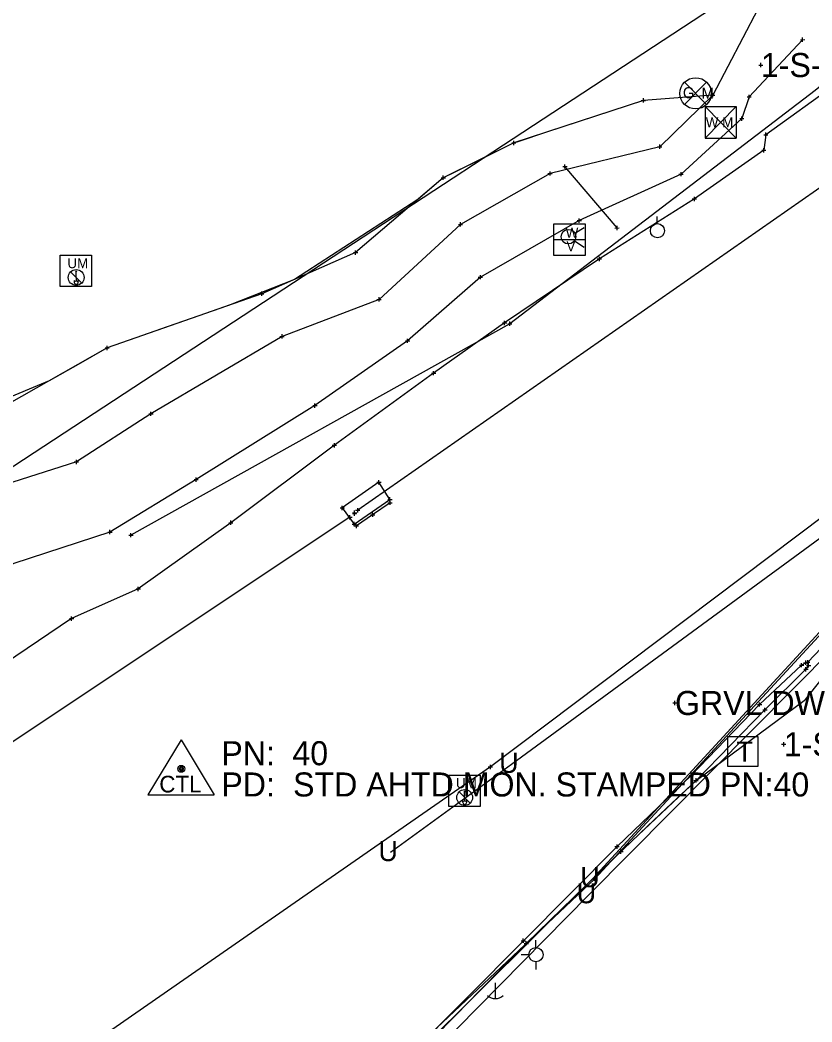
# Model space of a CAD drawing. Extents: x -1 to 1157254, y -1 to 2021979.
# Drawn here: x 1146373.4 to 1146610.6, y 2016480.3 to 2016780.3 of the extents above; entities that cross this region are included whole.
import ezdxf

# ---------------------------------------------------------------- set-up
doc = ezdxf.new("R2010")
doc.units = 0
for name, color, linetype in [('S_AREA_CALC', 7, 'Continuous'), ('S_BUILDING_ANNOT', 7, 'Continuous'), ('S_CAL_CORNER', 7, 'Continuous'), ('S_CAL_CORNER_ANNOT', 7, 'Continuous'), ('S_CATCH_BASIN', 7, 'Continuous'), ('S_CATCH_BASIN_ANNOT', 7, 'Continuous'), ('S_CONTOUR_ANNOT', 7, 'Continuous'), ('S_CONTOUR_MAJOR', 7, 'Continuous'), ('S_CTL_TABLE', 7, 'Continuous'), ('S_DITCHLINE', 7, 'Continuous'), ('S_DRIVEWAY_ANNOT', 7, 'Continuous'), ('S_DROP_INLET', 7, 'Continuous'), ('S_DROP_INLET_ANNOT', 7, 'Continuous'), ('S_DTM_PAVEMENT', 7, 'Continuous'), ('S_EDGE_BITUMINOUS_ANNOT', 7, 'Continuous'), ('S_ELECTRIC_UTILITIES', 7, 'Continuous'), ('S_FENCE', 7, 'Continuous'), ('S_GAS_PUMP_ISLAND_ANNOT', 7, 'Continuous'), ('S_GAS_UTILITIES', 7, 'Continuous'), ('S_GATE', 7, 'Continuous')]:
    doc.layers.add(name, color=color, linetype=linetype)

msp = doc.modelspace()

# ---------------------------------------------------------------- linework, layer by layer
at = {"layer": 'S_AREA_CALC'}
for p, q in [((1146421.68, 2016564.82), (1146411.65, 2016548.31)), ((1146421.68, 2016564.82), (1146431.5, 2016548.31)), ((1146411.65, 2016548.31), (1146431.5, 2016548.31))]:
    msp.add_line(p, q, dxfattribs=at)
for radius in [1.04, 0.609, 0.344]:
    msp.add_circle((1146421.68, 2016556.12), radius, dxfattribs=at)
at = {"layer": 'S_BUILDING_ANNOT'}
for p, q in [((1146594.63, 2016766.86), (1146595.9, 2016766.87)), ((1146595.27, 2016766.23), (1146595.27, 2016767.5)), ((1146595.27, 2016766.87), (1146595.27, 2016766.87)), ((1146535.95, 2016736.48), (1146537.22, 2016736.48)), ((1146536.59, 2016735.85), (1146536.58, 2016737.12)), ((1146536.59, 2016736.48), (1146536.59, 2016736.48)), ((1146551.58, 2016718.07), (1146552.85, 2016718.08)), ((1146552.22, 2016717.44), (1146552.22, 2016718.71)), ((1146552.22, 2016718.08), (1146552.22, 2016718.08)), ((1146519.44, 2016689.4), (1146520.71, 2016689.4)), ((1146520.07, 2016688.77), (1146520.07, 2016690.04)), ((1146520.07, 2016689.4), (1146520.07, 2016689.4)), ((1146480.24, 2016641.94), (1146481.51, 2016641.94)), ((1146480.87, 2016641.3), (1146480.87, 2016642.57)), ((1146480.87, 2016641.94), (1146480.87, 2016641.94)), ((1146484.19, 2016636.16), (1146484.18, 2016637.43)), ((1146469.25, 2016634.27), (1146470.52, 2016634.27)), ((1146469.88, 2016633.63), (1146469.88, 2016634.9)), ((1146469.88, 2016634.27), (1146469.88, 2016634.27)), ((1146474.52, 2016632.93), (1146474.52, 2016634.21)), ((1146483.55, 2016636.79), (1146484.82, 2016636.8)), ((1146484.19, 2016636.79), (1146484.19, 2016636.79)), ((1146471.55, 2016631.44), (1146472.82, 2016631.44)), ((1146472.19, 2016630.81), (1146472.19, 2016632.08)), ((1146472.19, 2016631.44), (1146472.19, 2016631.44)), ((1146472.92, 2016632.56), (1146474.2, 2016632.57)), ((1146472.96, 2016632.8), (1146474.23, 2016632.81)), ((1146473.56, 2016631.93), (1146473.56, 2016633.2)), ((1146473.56, 2016632.57), (1146473.56, 2016632.57)), ((1146473.6, 2016632.17), (1146473.59, 2016633.44)), ((1146473.6, 2016632.81), (1146473.6, 2016632.81)), ((1146473.88, 2016633.57), (1146475.16, 2016633.57)), ((1146474.52, 2016633.57), (1146474.52, 2016633.57)), ((1146472.85, 2016629.43), (1146474.12, 2016629.43)), ((1146473.48, 2016628.8), (1146473.48, 2016630.07)), ((1146473.48, 2016629.43), (1146473.48, 2016629.43)), ((1146405.96, 2016626.09), (1146407.23, 2016626.1)), ((1146406.59, 2016625.46), (1146406.59, 2016626.73)), ((1146406.59, 2016626.1), (1146406.59, 2016626.1)), ((1146606.85, 2016587.16), (1146608.12, 2016587.16)), ((1146607.49, 2016586.52), (1146607.48, 2016587.8)), ((1146607.49, 2016587.16), (1146607.49, 2016587.16)), ((1146608.06, 2016587.9), (1146609.33, 2016587.9)), ((1146608.7, 2016587.26), (1146608.7, 2016588.54)), ((1146608.7, 2016587.9), (1146608.7, 2016587.9)), ((1146608.71, 2016588.04), (1146609.99, 2016588.05)), ((1146608.78, 2016585.31), (1146608.78, 2016586.58)), ((1146608.95, 2016587.1), (1146610.22, 2016587.1)), ((1146609.35, 2016587.41), (1146609.35, 2016588.68)), ((1146609.35, 2016588.04), (1146609.35, 2016588.04)), ((1146609.58, 2016586.46), (1146609.58, 2016587.73)), ((1146609.58, 2016587.1), (1146609.58, 2016587.1)), ((1146608.14, 2016585.94), (1146609.41, 2016585.95)), ((1146608.78, 2016585.95), (1146608.78, 2016585.95)), ((1146568.9, 2016575.84), (1146570.18, 2016575.84)), ((1146569.54, 2016575.2), (1146569.54, 2016576.47)), ((1146569.54, 2016575.84), (1146569.54, 2016575.84)), ((1146594.26, 2016575.38), (1146595.53, 2016575.38)), ((1146594.9, 2016574.75), (1146594.89, 2016576.02)), ((1146594.9, 2016575.38), (1146594.9, 2016575.38)), ((1146596.5, 2016573.12), (1146596.5, 2016574.39)), ((1146595.86, 2016573.76), (1146597.13, 2016573.76)), ((1146596.5, 2016573.76), (1146596.5, 2016573.76)), ((1146601.49, 2016563.49), (1146602.77, 2016563.49)), ((1146602.13, 2016562.86), (1146602.13, 2016564.13)), ((1146602.13, 2016563.49), (1146602.13, 2016563.49)), ((1146513.63, 2016556.71), (1146514.9, 2016556.71)), ((1146514.27, 2016556.07), (1146514.26, 2016557.34)), ((1146514.26, 2016556.71), (1146514.26, 2016556.71)), ((1146573.79, 2016554.17), (1146575.06, 2016554.17)), ((1146574.43, 2016553.54), (1146574.42, 2016554.81)), ((1146574.42, 2016554.17), (1146574.42, 2016554.17)), ((1146575.86, 2016552.04), (1146575.86, 2016553.32)), ((1146575.22, 2016552.68), (1146576.49, 2016552.68)), ((1146575.86, 2016552.68), (1146575.86, 2016552.68)), ((1146551.56, 2016532.83), (1146552.83, 2016532.83)), ((1146552.2, 2016532.2), (1146552.19, 2016533.47)), ((1146552.2, 2016532.83), (1146552.2, 2016532.83)), ((1146552.72, 2016531.33), (1146553.99, 2016531.34)), ((1146553.36, 2016530.7), (1146553.35, 2016531.97)), ((1146553.36, 2016531.33), (1146553.36, 2016531.33)), ((1146544.89, 2016523.15), (1146546.16, 2016523.15)), ((1146545.53, 2016522.52), (1146545.52, 2016523.79)), ((1146545.52, 2016523.15), (1146545.52, 2016523.15)), ((1146524.14, 2016504), (1146524.13, 2016505.28)), ((1146523.5, 2016504.64), (1146524.77, 2016504.64)), ((1146524.14, 2016504.64), (1146524.14, 2016504.64)), ((1146524.37, 2016503.84), (1146525.65, 2016503.85)), ((1146525.01, 2016503.21), (1146525.01, 2016504.48)), ((1146525.01, 2016503.84), (1146525.01, 2016503.84))]:
    msp.add_line(p, q, dxfattribs=at)
at = {"layer": 'S_CAL_CORNER'}
for p, q in [((1146388.53, 2016704.93), (1146391.86, 2016701.6)), ((1146390.04, 2016705.16), (1146390.35, 2016705.16)), ((1146390.2, 2016703.27), (1146390.2, 2016705)), ((1146390.2, 2016703.27), (1146390.2, 2016702.21)), ((1146389.6, 2016702.36), (1146389.6, 2016702.18)), ((1146390.79, 2016702.37), (1146390.8, 2016702.14)), ((1146504.89, 2016549.22), (1146508.23, 2016545.89)), ((1146506.4, 2016549.45), (1146506.71, 2016549.45)), ((1146506.56, 2016547.55), (1146506.56, 2016549.29)), ((1146506.56, 2016547.55), (1146506.56, 2016546.5)), ((1146505.96, 2016546.65), (1146505.96, 2016546.47)), ((1146507.16, 2016546.65), (1146507.16, 2016546.43))]:
    msp.add_line(p, q, dxfattribs=at)
for points in [[(1146385.43, 2016709.93), (1146394.84, 2016709.93), (1146394.84, 2016700.51), (1146385.43, 2016700.51)], [(1146501.79, 2016554.21), (1146511.21, 2016554.21), (1146511.21, 2016544.8), (1146501.79, 2016544.8)]]:
    msp.add_lwpolyline(points, close=True, dxfattribs=at)
for centre in [(1146390.2, 2016703.27), (1146506.56, 2016547.55)]:
    msp.add_circle(centre, 2.36, dxfattribs=at)
for centre, radius, start, end in [((1146390.2, 2016705.16), 0.156, 180, 0), ((1146390.02, 2016702.76), 0.58, 223.1344, 287.472), ((1146390.37, 2016702.76), 0.58, 252.528, 316.8656), ((1146506.56, 2016549.45), 0.156, 180, 0), ((1146506.38, 2016547.05), 0.58, 223.1344, 287.472), ((1146506.73, 2016547.05), 0.58, 252.528, 316.8656)]:
    msp.add_arc(centre, radius, start, end, dxfattribs=at)
for centre in [(1146390.2, 2016702.02), (1146506.56, 2016546.31)]:
    msp.add_ellipse(centre, major_axis=(0, -0.82), ratio=0.744362, start_param=4.519801, end_param=8.000179, dxfattribs=at)
at = {"layer": 'S_CAL_CORNER_ANNOT'}
for p, q in [((1146572.43, 2016755.09), (1146579.04, 2016761.71)), ((1146572.43, 2016761.71), (1146579.04, 2016755.09))]:
    msp.add_line(p, q, dxfattribs=at)
msp.add_lwpolyline([(1146788.73, 2016902.43), (1146611.58, 2016759.23), (1146520.07, 2016689.4), (1146406.59, 2016626.1)], dxfattribs=at)
msp.add_circle((1146575.73, 2016758.4), 4.68, dxfattribs=at)
at = {"layer": 'S_CATCH_BASIN'}
for p, q in [((1146564.17, 2016719.39), (1146564.17, 2016721.5)), ((1146527.9, 2016502.58), (1146527.9, 2016504.82)), ((1146525.81, 2016500.45), (1146523.49, 2016500.45)), ((1146527.98, 2016496.03), (1146527.98, 2016498.36)), ((1146515.69, 2016492.06), (1146515.69, 2016487.33))]:
    msp.add_line(p, q, dxfattribs=at)
for centre in [(1146564.3, 2016717.25), (1146527.91, 2016500.47)]:
    msp.add_circle(centre, 2.13, dxfattribs=at)
msp.add_arc((1146515.75, 2016490.75), 3.41, 226.3972, 313.6028, dxfattribs=at)
at = {"layer": 'S_CATCH_BASIN_ANNOT'}
msp.add_lwpolyline([(1146585.41, 2016556.8), (1146585.41, 2016565.8), (1146594.41, 2016565.8), (1146594.41, 2016556.8)], close=True, dxfattribs=at)
at = {"layer": 'S_CONTOUR_ANNOT'}
for p, q in [((1146578.58, 2016754.47), (1146587.91, 2016754.47)), ((1146578.58, 2016754.47), (1146578.58, 2016744.98)), ((1146578.58, 2016754.47), (1146587.91, 2016744.98)), ((1146587.91, 2016754.47), (1146578.58, 2016744.98)), ((1146587.91, 2016754.47), (1146587.91, 2016744.98)), ((1146578.58, 2016744.98), (1146587.91, 2016744.98)), ((1146533.26, 2016719.29), (1146542.67, 2016719.29)), ((1146533.26, 2016709.88), (1146533.26, 2016719.29)), ((1146539.55, 2016716.53), (1146542.37, 2016718.26)), ((1146542.67, 2016719.29), (1146542.67, 2016709.88)), ((1146533.26, 2016714.61), (1146542.67, 2016714.61)), ((1146539.43, 2016714.22), (1146542.33, 2016712.29)), ((1146542.67, 2016709.88), (1146533.26, 2016709.88))]:
    msp.add_line(p, q, dxfattribs=at)
msp.add_lwpolyline([(1148171.01, 2018007.64), (1148133.82, 2017978.13), (1147884.86, 2017790.18), (1147810.34, 2017733.24), (1147725.21, 2017658.34), (1147638.36, 2017588.8), (1147507.67, 2017474.52), (1147125.41, 2017140.99), (1145970.62, 2016384.06)], dxfattribs=at)
msp.add_circle((1146537.65, 2016715.47), 2.18, dxfattribs=at)
at = {"layer": 'S_CTL_TABLE'}
for p, q in [((1146607.79, 2016773.84), (1146607.79, 2016775.11)), ((1146607.15, 2016774.47), (1146608.43, 2016774.48)), ((1146607.79, 2016774.47), (1146607.79, 2016774.47)), ((1146580.25, 2016757.84), (1146581.52, 2016757.84)), ((1146580.88, 2016757.21), (1146580.88, 2016758.48)), ((1146580.88, 2016757.84), (1146580.88, 2016757.84)), ((1146591.14, 2016757.31), (1146592.41, 2016757.31)), ((1146591.77, 2016756.67), (1146591.77, 2016757.95)), ((1146591.77, 2016757.31), (1146591.77, 2016757.31)), ((1146559.45, 2016756.28), (1146560.72, 2016756.29)), ((1146560.09, 2016755.65), (1146560.08, 2016756.92)), ((1146560.08, 2016756.29), (1146560.08, 2016756.29)), ((1146589.57, 2016750.21), (1146589.57, 2016751.48)), ((1146588.93, 2016750.84), (1146590.2, 2016750.84)), ((1146589.57, 2016750.84), (1146589.57, 2016750.84)), ((1146596.13, 2016746.01), (1146597.4, 2016746.01)), ((1146596.77, 2016745.37), (1146596.76, 2016746.64)), ((1146596.76, 2016746.01), (1146596.76, 2016746.01)), ((1146520.64, 2016743.54), (1146521.91, 2016743.54)), ((1146521.28, 2016742.9), (1146521.27, 2016744.17)), ((1146521.28, 2016743.54), (1146521.28, 2016743.54)), ((1146564.36, 2016742.42), (1146565.64, 2016742.42)), ((1146565, 2016741.78), (1146565, 2016743.06)), ((1146565, 2016742.42), (1146565, 2016742.42)), ((1146595.52, 2016741.34), (1146596.79, 2016741.34)), ((1146596.16, 2016740.7), (1146596.15, 2016741.97)), ((1146596.15, 2016741.34), (1146596.15, 2016741.34)), ((1146499.52, 2016733.12), (1146500.79, 2016733.12)), ((1146500.16, 2016732.48), (1146500.15, 2016733.75)), ((1146500.16, 2016733.12), (1146500.16, 2016733.12)), ((1146531.49, 2016734.39), (1146532.76, 2016734.39)), ((1146532.12, 2016733.75), (1146532.12, 2016735.02)), ((1146532.12, 2016734.39), (1146532.12, 2016734.39)), ((1146570.74, 2016734.21), (1146572.01, 2016734.21)), ((1146571.38, 2016733.57), (1146571.37, 2016734.84)), ((1146571.38, 2016734.21), (1146571.38, 2016734.21)), ((1146575.37, 2016726.16), (1146575.37, 2016727.43)), ((1146574.73, 2016726.79), (1146576.01, 2016726.8)), ((1146575.37, 2016726.8), (1146575.37, 2016726.8)), ((1146504.69, 2016719.17), (1146505.96, 2016719.17)), ((1146505.33, 2016718.54), (1146505.33, 2016719.81)), ((1146505.33, 2016719.17), (1146505.33, 2016719.17)), ((1146540.24, 2016720.3), (1146541.51, 2016720.31)), ((1146540.88, 2016719.67), (1146540.87, 2016720.94)), ((1146540.87, 2016720.31), (1146540.87, 2016720.31)), ((1146473.25, 2016710.73), (1146474.52, 2016710.73)), ((1146473.89, 2016710.09), (1146473.88, 2016711.36)), ((1146473.89, 2016710.73), (1146473.89, 2016710.73)), ((1146546.92, 2016708.16), (1146546.91, 2016709.43)), ((1146546.28, 2016708.8), (1146547.55, 2016708.8)), ((1146546.92, 2016708.8), (1146546.92, 2016708.8)), ((1146510.64, 2016703.36), (1146511.91, 2016703.36)), ((1146511.28, 2016702.72), (1146511.27, 2016704)), ((1146511.27, 2016703.36), (1146511.27, 2016703.36)), ((1146445.14, 2016698.38), (1146446.41, 2016698.38)), ((1146445.77, 2016697.74), (1146445.77, 2016699.02)), ((1146445.77, 2016698.38), (1146445.77, 2016698.38)), ((1146480.94, 2016696.04), (1146480.94, 2016697.32)), ((1146480.3, 2016696.68), (1146481.58, 2016696.68)), ((1146480.94, 2016696.68), (1146480.94, 2016696.68)), ((1146517.86, 2016689.65), (1146519.14, 2016689.65)), ((1146518.5, 2016689.01), (1146518.5, 2016690.29)), ((1146518.5, 2016689.65), (1146518.5, 2016689.65)), ((1146451.24, 2016685.6), (1146452.51, 2016685.61)), ((1146451.88, 2016684.97), (1146451.87, 2016686.24)), ((1146451.88, 2016685.6), (1146451.88, 2016685.6)), ((1146398.86, 2016682.16), (1146400.13, 2016682.16)), ((1146399.5, 2016681.52), (1146399.5, 2016682.8)), ((1146399.5, 2016682.16), (1146399.5, 2016682.16)), ((1146488.82, 2016684.29), (1146490.09, 2016684.29)), ((1146489.46, 2016683.65), (1146489.45, 2016684.92)), ((1146489.46, 2016684.29), (1146489.46, 2016684.29)), ((1146496.62, 2016674.59), (1146497.9, 2016674.6)), ((1146497.26, 2016673.96), (1146497.26, 2016675.23)), ((1146497.26, 2016674.6), (1146497.26, 2016674.6)), ((1146461.08, 2016664.88), (1146462.35, 2016664.88)), ((1146461.72, 2016664.25), (1146461.71, 2016665.52)), ((1146461.71, 2016664.88), (1146461.71, 2016664.88)), ((1146411.97, 2016662.43), (1146413.25, 2016662.44)), ((1146412.61, 2016661.8), (1146412.61, 2016663.07)), ((1146412.61, 2016662.43), (1146412.61, 2016662.43)), ((1146466.9, 2016653), (1146468.17, 2016653)), ((1146467.54, 2016652.37), (1146467.54, 2016653.64)), ((1146467.54, 2016653), (1146467.54, 2016653)), ((1146389.65, 2016648.03), (1146390.92, 2016648.04)), ((1146390.29, 2016647.4), (1146390.29, 2016648.67)), ((1146390.29, 2016648.03), (1146390.29, 2016648.03)), ((1146426.15, 2016642.09), (1146426.14, 2016643.36)), ((1146425.51, 2016642.72), (1146426.78, 2016642.73)), ((1146426.14, 2016642.72), (1146426.14, 2016642.72)), ((1146483.59, 2016635.78), (1146484.86, 2016635.78)), ((1146484.23, 2016635.15), (1146484.23, 2016636.42)), ((1146484.23, 2016635.78), (1146484.23, 2016635.78)), ((1146478.37, 2016632.2), (1146479.64, 2016632.21)), ((1146479.01, 2016631.57), (1146479, 2016632.84)), ((1146479, 2016632.21), (1146479, 2016632.21)), ((1146435.89, 2016629.8), (1146437.16, 2016629.8)), ((1146436.53, 2016629.16), (1146436.53, 2016630.44)), ((1146436.53, 2016629.8), (1146436.53, 2016629.8)), ((1146473.48, 2016628.86), (1146474.75, 2016628.87)), ((1146474.12, 2016628.23), (1146474.11, 2016629.5)), ((1146474.12, 2016628.86), (1146474.12, 2016628.86)), ((1146399.68, 2016627.03), (1146400.95, 2016627.04)), ((1146400.32, 2016626.4), (1146400.31, 2016627.67)), ((1146400.32, 2016627.04), (1146400.32, 2016627.04)), ((1146408.82, 2016609.35), (1146408.82, 2016610.62)), ((1146408.18, 2016609.98), (1146409.46, 2016609.98)), ((1146408.82, 2016609.98), (1146408.82, 2016609.98)), ((1146388.2, 2016601.1), (1146389.48, 2016601.11)), ((1146388.84, 2016600.47), (1146388.84, 2016601.74)), ((1146388.84, 2016601.11), (1146388.84, 2016601.11))]:
    msp.add_line(p, q, dxfattribs=at)
at = {"layer": 'S_DITCHLINE'}
for points in [[(1146676.34, 2016774.31), (1146474.52, 2016633.57)], [(1146472.19, 2016631.44), (1146267.75, 2016495.3)]]:
    msp.add_lwpolyline(points, dxfattribs=at)
at = {"layer": 'S_DRIVEWAY_ANNOT'}
for points in [[(1146609.58, 2016587.1), (1146608.78, 2016585.95), (1146596.5, 2016573.76), (1146575.86, 2016552.68), (1146553.36, 2016531.33), (1146525.01, 2016503.84), (1146490.8, 2016469.06), (1146473.28, 2016453.24), (1146444.21, 2016423.53), (1146420.15, 2016400.05), (1146385.91, 2016365.71)], [(1146608.7, 2016587.9), (1146607.49, 2016587.16), (1146594.9, 2016575.38), (1146574.42, 2016554.17), (1146552.2, 2016532.83), (1146524.14, 2016504.64), (1146489.96, 2016470.15), (1146472.62, 2016454.66), (1146443.06, 2016425.22), (1146419.92, 2016402.09), (1146386.65, 2016369.64)]]:
    msp.add_lwpolyline(points, dxfattribs=at)
at = {"layer": 'S_DROP_INLET'}
for points in [[(1148195.53, 2017935.77), (1148138.82, 2017892.99), (1148034.43, 2017809.59), (1147909.47, 2017714.32), (1147828.88, 2017654.71), (1147681.29, 2017538.62), (1147545.03, 2017424.01), (1147436.65, 2017326.84), (1147356.29, 2017257.74), (1147237.67, 2017148.84), (1147152.37, 2017082.27), (1147079.41, 2017020.24), (1146950.46, 2016911.58), (1146849.38, 2016826.65), (1146763.18, 2016745.2), (1146663.11, 2016665.75), (1146626.02, 2016634.68), (1146520.54, 2016557.46), (1146484.38, 2016531.03)], [(1146690.18, 2016667.93), (1146635.88, 2016622.11), (1146544.84, 2016523.22), (1146493.62, 2016472.25), (1146496.51, 2016468.3)], [(1146673.52, 2016650.06), (1146641.67, 2016617.07), (1146543.75, 2016518.41), (1146444.99, 2016418.15), (1146374.63, 2016345.67)]]:
    msp.add_lwpolyline(points, dxfattribs=at)
at = {"layer": 'S_DROP_INLET_ANNOT'}
msp.add_lwpolyline([(1146642.8, 2016623.21), (1146609.35, 2016588.04)], dxfattribs=at)
at = {"layer": 'S_DTM_PAVEMENT'}
msp.add_lwpolyline([(1146552.22, 2016718.08), (1146536.59, 2016736.48)], dxfattribs=at)
at = {"layer": 'S_EDGE_BITUMINOUS_ANNOT'}
for points in [[(1146607.79, 2016774.47), (1146591.77, 2016757.31), (1146589.57, 2016750.84), (1146571.38, 2016734.21), (1146540.87, 2016720.31), (1146511.27, 2016703.36), (1146489.46, 2016684.29), (1146461.71, 2016664.88), (1146426.14, 2016642.72), (1146400.32, 2016627.04), (1146371.51, 2016617.57), (1146342.07, 2016601.14), (1146301.38, 2016565.17), (1146260.21, 2016536.82), (1146241.57, 2016532.73), (1146220.45, 2016515.75), (1146193.63, 2016499.94)], [(1146617.85, 2016761.13), (1146596.76, 2016746.01), (1146596.15, 2016741.34), (1146575.37, 2016726.8), (1146546.92, 2016708.8), (1146518.5, 2016689.65), (1146497.26, 2016674.6), (1146467.54, 2016653), (1146436.53, 2016629.8), (1146408.82, 2016609.98), (1146388.84, 2016601.11), (1146355.38, 2016578.55), (1146316.44, 2016549.94), (1146267.98, 2016522.51), (1146251.21, 2016522.77), (1146225.59, 2016506.15), (1146208.66, 2016490.65)], [(1146580.88, 2016757.84), (1146565, 2016742.42), (1146532.12, 2016734.39), (1146505.33, 2016719.17), (1146480.94, 2016696.68), (1146451.88, 2016685.6), (1146412.61, 2016662.43), (1146390.29, 2016648.03), (1146359.24, 2016638.19), (1146334.12, 2016622.31), (1146288.5, 2016582.63), (1146250.82, 2016554.3), (1146230.59, 2016543.86), (1146211.46, 2016527.41), (1146171.26, 2016495.89)], [(1146560.08, 2016756.29), (1146521.28, 2016743.54), (1146500.16, 2016733.12), (1146473.89, 2016710.73), (1146445.77, 2016698.38), (1146399.5, 2016682.16), (1146364.94, 2016662.58), (1146339.15, 2016654.4), (1146317.6, 2016634.12), (1146278.95, 2016601.85), (1146242.52, 2016567.32), (1146224.24, 2016554.8), (1146200.88, 2016536.72)], [(1146484.23, 2016635.78), (1146479, 2016632.21), (1146474.12, 2016628.86)]]:
    msp.add_lwpolyline(points, dxfattribs=at)
at = {"layer": 'S_ELECTRIC_UTILITIES'}
msp.add_lwpolyline([(1146484.19, 2016636.79), (1146480.87, 2016641.94), (1146469.88, 2016634.27), (1146473.48, 2016629.43)], close=True, dxfattribs=at)
at = {"layer": 'S_FENCE'}
for points in [[(1148182.05, 2017918.06), (1148146.03, 2017882.74), (1148036.88, 2017800.65), (1147915.13, 2017710.9), (1147841.97, 2017653.39), (1147689.75, 2017529.1), (1147550.85, 2017419.33), (1147452.64, 2017321.35), (1147370.71, 2017243.52), (1147258.33, 2017138.3), (1147166.15, 2017078.02), (1147070.18, 2016992.83), (1146962.81, 2016905.87), (1146854.86, 2016827.91), (1146747.33, 2016742.81), (1146665.82, 2016680.99), (1146623.06, 2016638.6), (1146514.26, 2016556.71), (1146391.39, 2016471.4), (1146322.08, 2016427.51), (1146235.84, 2016374), (1146176.66, 2016335.01), (1146181.42, 2016326.5)], [(1146690.44, 2016667.45), (1146636.41, 2016621.57), (1146545.52, 2016523.15), (1146438.63, 2016422.41), (1146376.05, 2016354.06)]]:
    msp.add_lwpolyline(points, dxfattribs=at)
at = {"layer": 'S_GAS_PUMP_ISLAND_ANNOT'}
for points in [[(1146603.34, 2016800.85), (1146580.88, 2016757.84), (1146560.08, 2016756.29), (1146550.6, 2016753.17), (1146541.11, 2016750.05), (1146531.62, 2016746.94), (1146522.14, 2016743.82), (1146521.28, 2016743.54), (1146512.33, 2016739.12), (1146503.39, 2016734.71), (1146500.16, 2016733.12), (1146492.55, 2016726.64), (1146455.57, 2016702.68), (1146436.35, 2016695.08), (1146426.93, 2016691.77), (1146417.5, 2016688.47), (1146408.08, 2016685.17), (1146399.5, 2016682.16), (1146390.8, 2016677.23), (1146382.1, 2016672.3), (1146339.15, 2016654.4)], [(1146496.98, 2016475.35), (1146503.99, 2016482.47), (1146511, 2016489.6), (1146518, 2016496.72), (1146531.83, 2016510.46), (1146539, 2016517.42), (1146546.18, 2016524.37), (1146554.1, 2016532.04), (1146561.35, 2016538.92), (1146568.6, 2016545.8), (1146575.86, 2016552.68), (1146608.62, 2016576.91), (1146613.32, 2016582.73), (1146643.88, 2016613.13), (1146668.98, 2016631.33), (1146691.72, 2016671), (1146698.96, 2016677.9), (1146706.19, 2016684.8), (1146713.42, 2016691.7), (1146727.66, 2016704.55), (1146735.28, 2016711.02)]]:
    msp.add_lwpolyline(points, dxfattribs=at)

# ---------------------------------------------------------------- texts
at = {"layer": 'S_AREA_CALC'}
msp.add_text('CTL', height=4.998, dxfattribs=at).set_placement((1146415.1, 2016549.05))
at = {"layer": 'S_CAL_CORNER'}
for p in [(1146387.58, 2016706.04), (1146503.94, 2016550.33)]:
    msp.add_text('UM', height=2.999, dxfattribs=at).set_placement(p)
at = {"layer": 'S_CAL_CORNER_ANNOT'}
for s, p in [('G', (1146571.92, 2016756.93)), ('M', (1146577.48, 2016756.83))]:
    msp.add_text(s, height=3.3, dxfattribs=at).set_placement(p)
at = {"layer": 'S_CATCH_BASIN_ANNOT'}
msp.add_text('T', height=6, dxfattribs=at).set_placement((1146587.98, 2016558.3))
at = {"layer": 'S_CONTOUR_ANNOT'}
for s, height, p in [('W M', 2.999, (1146578.78, 2016748.23)), ('W', 3, (1146536.81, 2016715.14)), ('V', 3, (1146537.05, 2016711.08))]:
    msp.add_text(s, height=height, dxfattribs=at).set_placement(p)
at = {"layer": 'S_CONTOUR_MAJOR'}
for p in [(1146516.91, 2016554.92), (1146480.75, 2016528.49), (1146541.21, 2016520.68), (1146540.12, 2016515.87)]:
    msp.add_text('U', height=6, dxfattribs=at).set_placement(p)
at = {"layer": 'S_GAS_UTILITIES'}
for s, p in [('PN: ', (1146433.68, 2016557.2)), ('40', (1146454.95, 2016557.2)), ('PD: ', (1146433.68, 2016547.84)), ('STD AHTD MON. STAMPED PN:40', (1146455.16, 2016547.84))]:
    msp.add_text(s, height=7.2, dxfattribs=at).set_placement(p)
at = {"layer": 'S_GATE'}
for s, p in [('1-S-B', (1146595.27, 2016763.27)), ('GRVL DW', (1146569.54, 2016572.24)), ('1-S-MTL', (1146602.13, 2016559.89))]:
    msp.add_text(s, height=7.2, dxfattribs=at).set_placement(p)

doc.saveas('drawing.dxf')
